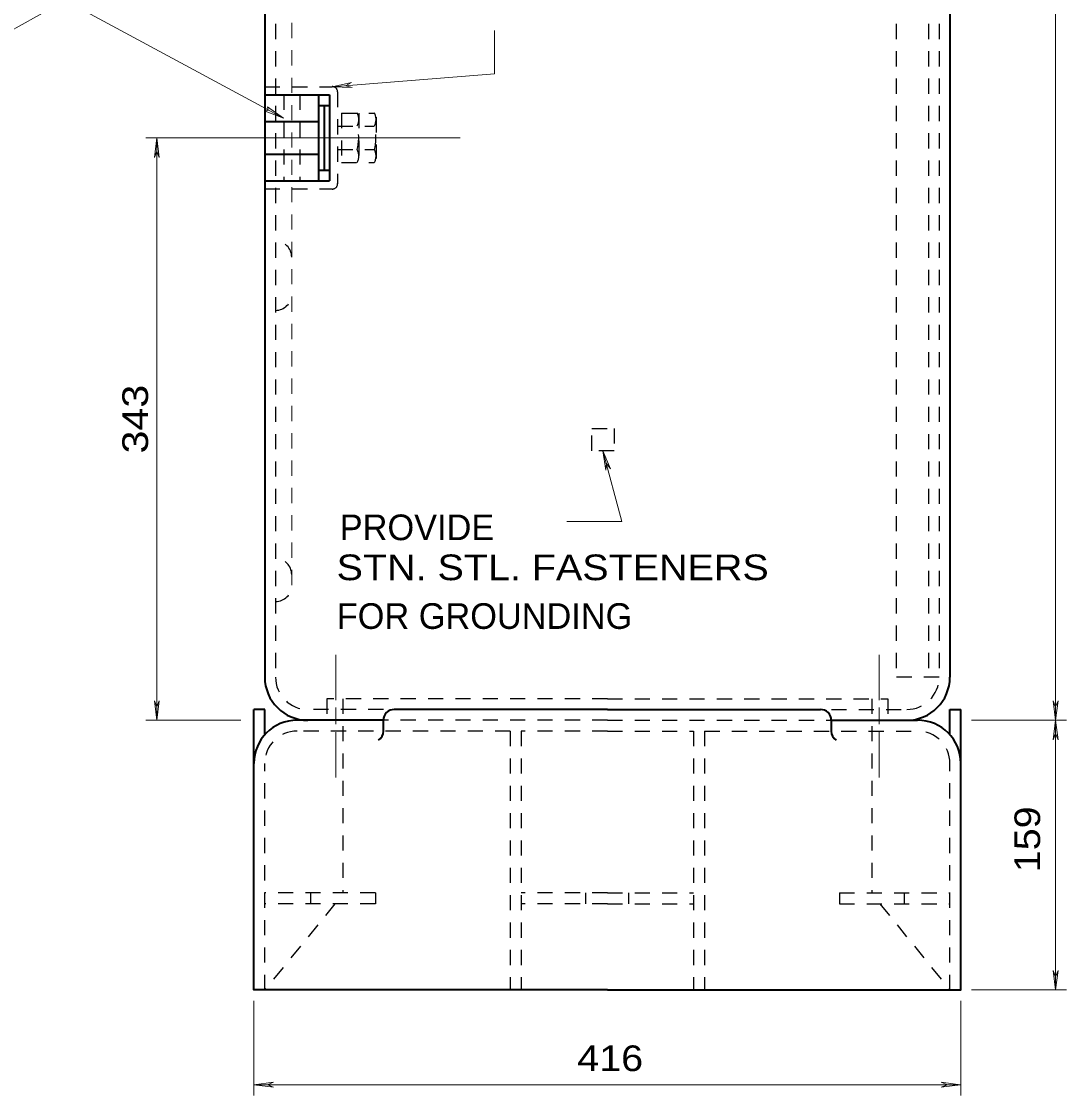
# Model space of a CAD drawing. Extents: x 312583 to 312854, y 144419 to 144597.
# Drawn here: x 312675.3 to 312706.24, y 144453.98 to 144485.79 of the extents above; entities that cross this region are included whole.
import ezdxf
from ezdxf.enums import TextEntityAlignment as Align

# ---------------------------------------------------------------- set-up
doc = ezdxf.new("R2010")
doc.units = 0
doc.header["$LTSCALE"] = 0.3
doc.linetypes.add('SHORT_DASHED', pattern=[2.7, 1.5, -1.2])
doc.layers.add('1', color=7, linetype='Continuous', lineweight=25)
doc.layers.add('2', color=7, linetype='Continuous', lineweight=13)

msp = doc.modelspace()

# ---------------------------------------------------------------- linework, layer by layer
at = {"layer": '1', "lineweight": 40}
for p, q in [((312682.5018, 144518.1223), (312682.5018, 144466.3723)), ((312702.7878, 144518.1223), (312702.7878, 144466.3723)), ((312682.5018, 144483.6223), (312684.4184, 144483.6223)), ((312684.0964, 144483.6223), (312684.0964, 144481.0693)), ((312684.4184, 144483.6223), (312684.4184, 144481.0693)), ((312684.0964, 144483.308), (312684.4184, 144483.308)), ((312684.2574, 144483.308), (312684.2574, 144481.3913)), ((312682.5018, 144482.825), (312684.0964, 144482.825)), ((312682.5018, 144481.8667), (312684.0964, 144481.8667)), ((312684.0964, 144481.3913), (312684.4184, 144481.3913)), ((312682.5018, 144481.0693), (312684.4184, 144481.0693)), ((312682.5018, 144465.414), (312682.1798, 144465.414)), ((312682.5018, 144464.6627), (312682.5018, 144465.414)), ((312692.6448, 144465.414), (312686.3351, 144465.414)), ((312692.6448, 144465.414), (312698.9544, 144465.414)), ((312702.7878, 144465.414), (312703.1098, 144465.414)), ((312702.7878, 144464.6627), (312702.7878, 144465.414)), ((312686.0131, 144465.0997), (312683.4601, 144465.0997)), ((312686.0131, 144464.7777), (312686.0131, 144465.0997)), ((312699.2764, 144465.0997), (312701.8294, 144465.0997)), ((312699.2764, 144464.7777), (312699.2764, 144465.0997))]:
    msp.add_line(p, q, dxfattribs=at)
at = {"layer": '1', "linetype": 'SHORT_DASHED'}
for p, q in [((312682.8238, 144518.1223), (312682.8238, 144466.3723)), ((312701.1931, 144518.1223), (312701.1931, 144466.3723)), ((312702.1514, 144518.1223), (312702.1514, 144466.3723)), ((312702.4658, 144518.1223), (312702.4658, 144466.3723)), ((312682.5018, 144483.86), (312684.4951, 144483.86)), ((312683.0614, 144483.6223), (312683.0614, 144481.0693)), ((312683.5368, 144483.6223), (312683.5368, 144481.0693)), ((312684.6561, 144483.7067), (312684.6561, 144480.985)), ((312684.7711, 144483.078), (312685.7448, 144483.078)), ((312684.7711, 144483.078), (312684.7711, 144481.6137)), ((312685.2848, 144483.078), (312685.2848, 144481.6137)), ((312685.7984, 144482.9553), (312685.7984, 144481.7363)), ((312684.6561, 144482.6947), (312685.7448, 144482.6947)), ((312684.6561, 144481.997), (312685.7448, 144481.997)), ((312684.7711, 144481.6137), (312685.7448, 144481.6137)), ((312682.5018, 144480.8317), (312684.4951, 144480.8317)), ((312702.4658, 144466.3723), (312701.1931, 144466.3723)), ((312684.8171, 144465.736), (312684.8171, 144459.986)), ((312700.4724, 144465.736), (312700.4724, 144459.986)), ((312686.0131, 144465.414), (312683.7821, 144465.414)), ((312699.2764, 144465.414), (312701.5074, 144465.414)), ((312692.6448, 144465.0997), (312686.0131, 144465.0997)), ((312692.6448, 144465.0997), (312699.2764, 144465.0997)), ((312689.7698, 144464.7777), (312683.4601, 144464.7777)), ((312689.7698, 144464.7777), (312689.7698, 144457.111)), ((312690.0918, 144464.7777), (312690.0918, 144457.111)), ((312692.6448, 144464.7777), (312690.0918, 144464.7777)), ((312692.6448, 144464.7777), (312695.1978, 144464.7777)), ((312695.1978, 144464.7777), (312695.1978, 144457.111)), ((312695.5198, 144464.7777), (312695.5198, 144457.111)), ((312695.5198, 144464.7777), (312701.8294, 144464.7777)), ((312682.5018, 144457.111), (312682.5018, 144463.8193)), ((312702.7878, 144457.111), (312702.7878, 144463.8193)), ((312685.7754, 144459.986), (312682.5018, 144459.986)), ((312683.8588, 144459.986), (312683.8588, 144459.664)), ((312685.7754, 144459.986), (312685.7754, 144459.664)), ((312692.6448, 144459.986), (312690.0918, 144459.986)), ((312692.0084, 144459.664), (312692.0084, 144459.986)), ((312692.6448, 144459.986), (312695.1978, 144459.986)), ((312693.2811, 144459.664), (312693.2811, 144459.986)), ((312699.5141, 144459.986), (312702.7878, 144459.986)), ((312699.5141, 144459.986), (312699.5141, 144459.664)), ((312701.4308, 144459.986), (312701.4308, 144459.664)), ((312685.7754, 144459.664), (312682.5018, 144459.664)), ((312684.5794, 144459.664), (312682.5018, 144457.111)), ((312692.6448, 144459.664), (312690.0918, 144459.664)), ((312692.6448, 144459.664), (312695.1978, 144459.664)), ((312699.5141, 144459.664), (312702.7878, 144459.664)), ((312700.7101, 144459.664), (312702.7878, 144457.111))]:
    msp.add_line(p, q, dxfattribs=at)
at = {"layer": '1', "linetype": 'SHORT_DASHED', "lineweight": 13}
msp.add_line((312683.2991, 144516.5277), (312683.2991, 144469.0863), dxfattribs=at)
at = {"layer": '1', "linetype": 'SHORT_DASHED'}
for points in [[(312692.6448, 144465.736), (312684.3418, 144465.736), (312684.3418, 144465.0997)], [(312692.6448, 144465.736), (312700.9478, 144465.736), (312700.9478, 144465.0997)]]:
    msp.add_lwpolyline(points, dxfattribs=at)
at = {"layer": '1', "lineweight": 40}
for points in [[(312692.6448, 144457.111), (312682.1798, 144457.111), (312682.1798, 144465.414)], [(312692.6448, 144457.111), (312703.1098, 144457.111), (312703.1098, 144465.414)]]:
    msp.add_lwpolyline(points, dxfattribs=at)
at = {"layer": '1', "linetype": 'SHORT_DASHED'}
for centre, radius, start, end in [((312684.4977, 144483.7041), 0.1597, 0, 90), ((312684.4977, 144480.9888), 0.1597, 270, 0), ((312682.8199, 144478.8115), 0.4792, 360, 90), ((312682.8199, 144477.7152), 0.4792, 270, 0), ((312682.8199, 144469.4096), 0.4792, 360, 90), ((312682.8199, 144469.0902), 0.4792, 270, 0), ((312683.7783, 144466.3749), 0.9583, 180, 270), ((312701.5087, 144466.3749), 0.9583, 270, 0), ((312683.4588, 144463.8193), 0.9583, 90, 180), ((312701.8282, 144463.8193), 0.9583, 0, 90)]:
    msp.add_arc(centre, radius, start, end, dxfattribs=at)
at = {"layer": '1', "lineweight": 40}
for centre, radius, start, end in [((312683.7783, 144466.3749), 1.2778, 180, 270), ((312701.5087, 144466.3749), 1.2778, 270, 0), ((312686.3338, 144465.0971), 0.3194, 90, 180), ((312698.9532, 144465.0971), 0.3194, 0, 90), ((312683.4588, 144463.8193), 1.2778, 90, 180), ((312701.8282, 144463.8193), 1.2778, 0, 90), ((312685.6949, 144464.7777), 0.3194, 302.70422, 0), ((312699.592, 144464.7777), 0.3194, 180, 237.29578)]:
    msp.add_arc(centre, radius, start, end, dxfattribs=at)
at = {"layer": '2'}
for p, q in [((312705.9158, 144465.0997), (312705.9158, 144519.4027)), ((312684.4951, 144483.86), (312685.0701, 144483.9827)), ((312684.4951, 144483.86), (312685.0854, 144483.837)), ((312685.0701, 144483.9827), (312684.8938, 144483.8907)), ((312685.0854, 144483.837), (312684.8938, 144483.8907)), ((312688.2901, 144482.3497), (312678.9828, 144482.3497)), ((312679.3048, 144482.3497), (312679.2358, 144481.767)), ((312679.3048, 144465.0997), (312679.3048, 144482.3497)), ((312679.3048, 144482.3497), (312679.3738, 144481.767)), ((312679.2358, 144481.767), (312679.3048, 144481.951)), ((312679.3738, 144481.767), (312679.3048, 144481.951)), ((312692.5144, 144473.0807), (312692.5988, 144472.5057)), ((312692.5144, 144473.0807), (312692.7368, 144472.544)), ((312692.5144, 144473.0807), (312693.0741, 144470.9877)), ((312692.5988, 144472.5057), (312692.6141, 144472.705)), ((312692.7368, 144472.544), (312692.6141, 144472.705)), ((312691.4411, 144470.9877), (312693.0741, 144470.9877)), ((312684.6024, 144467.0317), (312684.6024, 144465.69)), ((312700.6871, 144467.0317), (312700.6871, 144465.69)), ((312679.2358, 144465.6747), (312679.3048, 144465.4907)), ((312679.3048, 144465.0997), (312679.2358, 144465.6747)), ((312679.3738, 144465.6747), (312679.3048, 144465.4907)), ((312679.3048, 144465.0997), (312679.3738, 144465.6747)), ((312705.8468, 144465.6747), (312705.9158, 144465.4907)), ((312705.9158, 144465.0997), (312705.8468, 144465.6747)), ((312705.9924, 144465.6747), (312705.9158, 144465.4907)), ((312705.9158, 144465.0997), (312705.9924, 144465.6747)), ((312684.6024, 144464.9847), (312684.6024, 144465.4753)), ((312700.6871, 144464.9847), (312700.6871, 144465.4753)), ((312681.7964, 144465.0997), (312678.9828, 144465.0997)), ((312703.4241, 144465.0997), (312706.2378, 144465.0997)), ((312705.9158, 144465.0997), (312705.8468, 144464.517)), ((312705.9158, 144457.111), (312705.9158, 144465.0997)), ((312705.9158, 144465.0997), (312705.9924, 144464.517)), ((312684.6024, 144463.4053), (312684.6024, 144464.747)), ((312700.6871, 144463.4053), (312700.6871, 144464.747)), ((312705.8468, 144464.517), (312705.9158, 144464.701)), ((312705.9924, 144464.517), (312705.9158, 144464.701)), ((312705.8468, 144457.686), (312705.9158, 144457.502)), ((312705.9158, 144457.111), (312705.8468, 144457.686)), ((312705.9924, 144457.686), (312705.9158, 144457.502)), ((312705.9158, 144457.111), (312705.9924, 144457.686)), ((312703.4241, 144457.111), (312706.2378, 144457.111)), ((312682.1798, 144456.789), (312682.1798, 144453.983)), ((312703.1098, 144456.789), (312703.1098, 144453.983)), ((312682.1798, 144454.2973), (312682.7624, 144454.374)), ((312682.1798, 144454.2973), (312703.1021, 144454.2973)), ((312682.1798, 144454.2973), (312682.7624, 144454.2283)), ((312682.7624, 144454.374), (312682.5784, 144454.2973)), ((312682.7624, 144454.2283), (312682.5784, 144454.2973)), ((312702.5271, 144454.374), (312702.7111, 144454.2973)), ((312703.1021, 144454.2973), (312702.5271, 144454.374)), ((312702.5271, 144454.2283), (312702.7111, 144454.2973)), ((312703.1021, 144454.2973), (312702.5271, 144454.2283))]:
    msp.add_line(p, q, dxfattribs=at)
for points in [[(312670.2121, 144482.8633), (312676.5908, 144486.413), (312683.0538, 144482.9247)], [(312689.3021, 144485.5237), (312689.3021, 144484.2433), (312684.4951, 144483.86)]]:
    msp.add_lwpolyline(points, dxfattribs=at)
msp.add_lwpolyline([(312682.5861, 144483.262), (312683.0538, 144482.9247), (312682.5171, 144483.1317), (312682.6014, 144483.17)], close=True, dxfattribs=at)
at = {"layer": '2', "linetype": 'SHORT_DASHED', "lineweight": 25}
msp.add_lwpolyline([(312692.1848, 144473.74), (312692.8441, 144473.74), (312692.8441, 144473.0807), (312692.1848, 144473.0807)], close=True, dxfattribs=at)
for centre, radius, start, end in [((312684.8828, 144482.8902), 0.402, 331.52722, 28.47277), ((312685.3939, 144482.8902), 0.402, 331.52722, 28.47277), ((312683.9171, 144482.3471), 1.3651, 345.08374, 14.91626), ((312684.4282, 144482.3471), 1.3651, 345.08374, 14.91626), ((312684.8828, 144481.8041), 0.402, 331.52722, 28.47277), ((312685.3939, 144481.8041), 0.402, 331.52722, 28.47277)]:
    msp.add_arc(centre, radius, start, end, dxfattribs=at)

# ---------------------------------------------------------------- texts
at = {"layer": '2'}
for s, width, p in [('343 ', 1.2, (312679.0451, 144474.1853)), ('159 ', 1.15, (312705.4568, 144461.7326))]:
    msp.add_text(s, height=0.76, rotation=90, dxfattribs=dict(at, width=width)).set_placement(p, align=Align.CENTER)
for s, p in [('PROVIDE', (312687.0092, 144470.4305)), ('FOR GROUNDING', (312689.0079, 144467.8032))]:
    msp.add_text(s, height=0.76, dxfattribs=at).set_placement(p, align=Align.CENTER)
at = {"layer": '2', "width": 1.15}
for s, p in [('STN. STL. FASTENERS', (312691.0255, 144469.2456)), ('416 ', (312692.8898, 144454.7061))]:
    msp.add_text(s, height=0.76, dxfattribs=at).set_placement(p, align=Align.CENTER)

doc.saveas('drawing.dxf')
